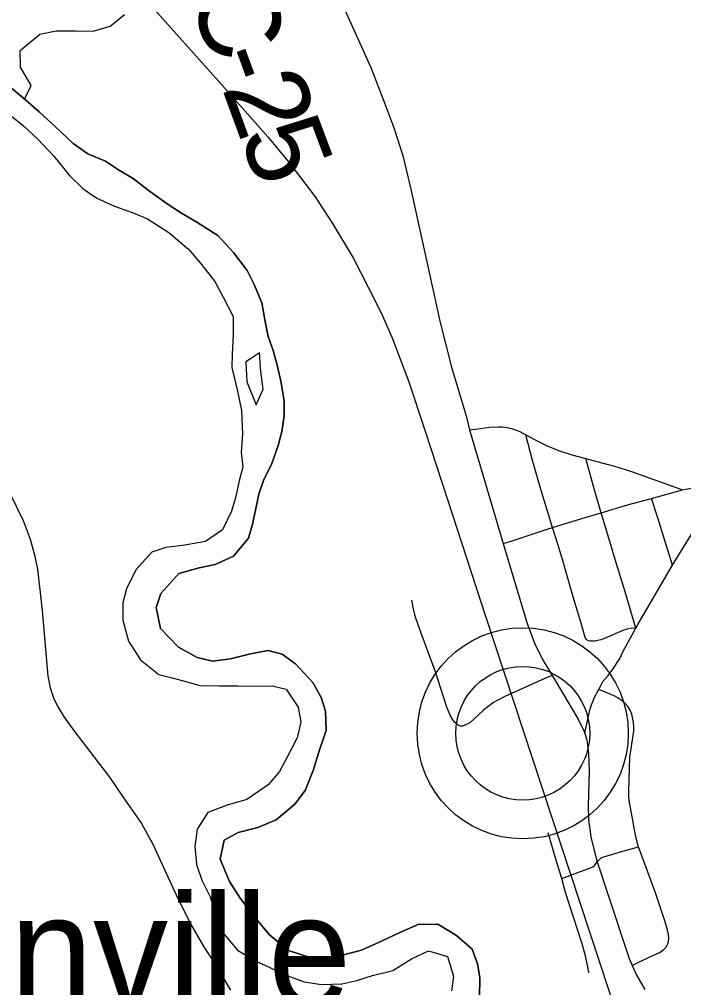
# Model space of a CAD drawing. Extents: x 0 to 34, y 0 to 22.
# Drawn here: x 6.658 to 7.127, y 19.04 to 19.722 of the extents above; entities that cross this region are included whole.
import ezdxf

# ---------------------------------------------------------------- set-up
doc = ezdxf.new("R2010")
doc.units = 0
for name, color, linetype in [('GM_X_County_Road', 7, 'Continuous'), ('GM_X_County_Road_Text', 7, 'Continuous'), ('GM_X_Major_River', 7, 'Continuous'), ('GM_X_Minor_River', 7, 'Continuous'), ('GM_X_Rail_Line', 7, 'Continuous'), ('GM_X_Township_Road', 7, 'Continuous'), ('GM_X_Unincorporated', 7, 'Continuous'), ('GM_X_Unincorporated_Location', 7, 'Continuous'), ('GM_X_Unincorporated_Text', 7, 'Continuous')]:
    doc.layers.add(name, color=color, linetype=linetype)

msp = doc.modelspace()

# ---------------------------------------------------------------- linework, layer by layer
at = {"layer": 'GM_X_County_Road'}
for points in [[(6.8659, 19.90723), (6.85719, 19.88713), (6.85353, 19.87534), (6.85094, 19.86327), (6.84944, 19.85102), (6.84896, 19.83868), (6.84959, 19.82636), (6.85148, 19.81418), (6.85452, 19.80221), (6.86073, 19.78792), (6.86585, 19.77648), (6.87184, 19.76461), (6.88429, 19.73703), (6.90598, 19.68854), (6.91561, 19.66344)], [(6.91561, 19.66344), (6.92203, 19.6467), (6.92852, 19.62638), (6.93433, 19.60265), (6.95482, 19.50873), (6.96301, 19.47731), (6.97326, 19.44282), (6.97549, 19.433), (6.99937, 19.35289), (7.01595, 19.29727), (7.02129, 19.28279), (7.02672, 19.27172), (7.03375, 19.26001), (7.0411, 19.24777), (7.05229, 19.22905), (7.0563, 19.22053), (7.05679, 19.21894), (7.05819, 19.21449), (7.05957, 19.20512), (7.05987, 19.19261), (7.05914, 19.16778), (7.05947, 19.15855), (7.06113, 19.14633), (7.06349, 19.13649), (7.06551, 19.12868), (7.07307, 19.10585), (7.08809, 19.06055), (7.0903, 19.05557), (7.09309, 19.04928), (7.09919, 19.03857)]]:
    msp.add_lwpolyline(points, dxfattribs=at)
at = {"layer": 'GM_X_Major_River'}
for p, q in [((6.66265, 19.66554), (6.64969, 19.67641)), ((6.67218, 19.65729), (6.66265, 19.66554)), ((6.64796, 19.65783), (6.6613, 19.64734)), ((6.68362, 19.64678), (6.67218, 19.65729)), ((6.6613, 19.64734), (6.67122, 19.63795)), ((6.69621, 19.63477), (6.68362, 19.64678)), ((6.67122, 19.63795), (6.68267, 19.62593)), ((6.70649, 19.62767), (6.69621, 19.63477)), ((6.71902, 19.62247), (6.70649, 19.62767)), ((6.68267, 19.62593), (6.69376, 19.61239)), ((6.72892, 19.61574), (6.71902, 19.62247)), ((6.73843, 19.61014), (6.72892, 19.61574)), ((6.69376, 19.61239), (6.7033, 19.603)), ((6.74909, 19.60191), (6.73843, 19.61014)), ((6.7033, 19.603), (6.71282, 19.59627)), ((6.76318, 19.5918), (6.74909, 19.60191)), ((6.71282, 19.59627), (6.72535, 19.5907)), ((6.72535, 19.5907), (6.73864, 19.58589)), ((6.73864, 19.58589), (6.74851, 19.58182)), ((6.77269, 19.58583), (6.76318, 19.5918)), ((6.78334, 19.57948), (6.77269, 19.58583)), ((6.74851, 19.58182), (6.76373, 19.5721)), ((6.79818, 19.57014), (6.78334, 19.57948)), ((6.76373, 19.5721), (6.77784, 19.5601)), ((6.80926, 19.55812), (6.79818, 19.57014)), ((6.77784, 19.5601), (6.78663, 19.54957)), ((6.81883, 19.54532), (6.80926, 19.55812)), ((6.78663, 19.54957), (6.79619, 19.53753)), ((6.82383, 19.53551), (6.81883, 19.54532)), ((6.79619, 19.53753), (6.80196, 19.5266)), ((6.82924, 19.52268), (6.82383, 19.53551)), ((6.80196, 19.5266), (6.80889, 19.51302)), ((6.83162, 19.50944), (6.82924, 19.52268)), ((6.80889, 19.51302), (6.809, 19.50014)), ((6.83361, 19.49884), (6.83162, 19.50944)), ((6.809, 19.50014), (6.80836, 19.48649)), ((6.8371, 19.48902), (6.83361, 19.49884)), ((6.80836, 19.48649), (6.80807, 19.47701)), ((6.82113, 19.48306), (6.81787, 19.48089)), ((6.82765, 19.48742), (6.82113, 19.48306)), ((6.82852, 19.47417), (6.82765, 19.48742)), ((6.84022, 19.47768), (6.8371, 19.48902)), ((6.80807, 19.47701), (6.812, 19.46037)), ((6.81787, 19.48089), (6.81875, 19.46688)), ((6.84258, 19.46747), (6.84022, 19.47768)), ((6.83015, 19.46167), (6.82852, 19.47417)), ((6.81875, 19.46688), (6.8252, 19.45072)), ((6.84498, 19.45347), (6.84258, 19.46747)), ((6.812, 19.46037), (6.81477, 19.44676)), ((6.8252, 19.45072), (6.83015, 19.46167)), ((6.84507, 19.44286), (6.84498, 19.45347)), ((6.81477, 19.44676), (6.81567, 19.43009)), ((6.84327, 19.43186), (6.84507, 19.44286)), ((6.81567, 19.43009), (6.81465, 19.4172)), ((6.84071, 19.42198), (6.84327, 19.43186)), ((6.83628, 19.40943), (6.84071, 19.42198)), ((6.81465, 19.4172), (6.81587, 19.40698)), ((6.83033, 19.39725), (6.83628, 19.40943)), ((6.81587, 19.40698), (6.81331, 19.3971)), ((6.81331, 19.3971), (6.81076, 19.38533)), ((6.82701, 19.38775), (6.83033, 19.39725)), ((6.82484, 19.37636), (6.82701, 19.38775)), ((6.81076, 19.38533), (6.80782, 19.37583)), ((6.80782, 19.37583), (6.8015, 19.36251)), ((6.82265, 19.36649), (6.82484, 19.37636)), ((6.8015, 19.36251), (6.78946, 19.35444)), ((6.81971, 19.35661), (6.82265, 19.36649)), ((6.78946, 19.35444), (6.7736, 19.35164)), ((6.80923, 19.34401), (6.81971, 19.35661)), ((6.75169, 19.3469), (6.74045, 19.33429)), ((6.7615, 19.35002), (6.75169, 19.3469)), ((6.7736, 19.35164), (6.7615, 19.35002)), ((6.79641, 19.33821), (6.80923, 19.34401)), ((6.74045, 19.33429), (6.73376, 19.32096)), ((6.77074, 19.33191), (6.78509, 19.33583)), ((6.78509, 19.33583), (6.79641, 19.33821)), ((6.758, 19.31778), (6.77074, 19.33191)), ((6.73376, 19.32096), (6.73119, 19.31109)), ((6.75468, 19.30789), (6.758, 19.31778)), ((6.73119, 19.31109), (6.7313, 19.29896)), ((6.75784, 19.29314), (6.75468, 19.30789)), ((6.7313, 19.29896), (6.73521, 19.28422)), ((6.77044, 19.27999), (6.75784, 19.29314)), ((6.73521, 19.28422), (6.74365, 19.27103)), ((6.78374, 19.27254), (6.77044, 19.27999)), ((6.79436, 19.26998), (6.78374, 19.27254)), ((6.80721, 19.27161), (6.79436, 19.26998)), ((6.82118, 19.27515), (6.80721, 19.27161)), ((6.83364, 19.27754), (6.82118, 19.27515)), ((6.8435, 19.27497), (6.83364, 19.27754)), ((6.85302, 19.26824), (6.8435, 19.27497)), ((6.74365, 19.27103), (6.75661, 19.26054)), ((6.86524, 19.25509), (6.85302, 19.26824)), ((6.75661, 19.26054), (6.76608, 19.25835)), ((6.76608, 19.25835), (6.77557, 19.25579)), ((6.77557, 19.25579), (6.78543, 19.25285)), ((6.78543, 19.25285), (6.79905, 19.25259)), ((6.79905, 19.25259), (6.81229, 19.25271)), ((6.81229, 19.25271), (6.8263, 19.25246)), ((6.8263, 19.25246), (6.83651, 19.25255)), ((6.83651, 19.25255), (6.84637, 19.25037)), ((6.87101, 19.24453), (6.86524, 19.25509)), ((6.84637, 19.25037), (6.8548, 19.23756)), ((6.87412, 19.23471), (6.87101, 19.24453)), ((6.8548, 19.23756), (6.85679, 19.22697)), ((6.87462, 19.22107), (6.87412, 19.23471)), ((6.85679, 19.22697), (6.85423, 19.21596)), ((6.87019, 19.20814), (6.87462, 19.22107)), ((6.85423, 19.21596), (6.84753, 19.20339)), ((6.84753, 19.20339), (6.84158, 19.19235)), ((6.86541, 19.19294), (6.87019, 19.20814)), ((6.84158, 19.19235), (6.83371, 19.1828)), ((6.85985, 19.17887), (6.86541, 19.19294)), ((6.83371, 19.1828), (6.81867, 19.17243)), ((6.85237, 19.16933), (6.85985, 19.17887)), ((6.81867, 19.17243), (6.8047, 19.16852)), ((6.83922, 19.15822), (6.85237, 19.16933)), ((6.79113, 19.16347), (6.78366, 19.15165)), ((6.8047, 19.16852), (6.79113, 19.16347)), ((6.82641, 19.1528), (6.83922, 19.15822)), ((6.78366, 19.15165), (6.78188, 19.13951)), ((6.80265, 19.14387), (6.81244, 19.14926)), ((6.81244, 19.14926), (6.82641, 19.1528)), ((6.79974, 19.13058), (6.80265, 19.14387)), ((6.78188, 19.13951), (6.78312, 19.12664)), ((6.80631, 19.11472), (6.79974, 19.13058)), ((6.78312, 19.12664), (6.787, 19.11568)), ((6.787, 19.11568), (6.79278, 19.10399)), ((6.81398, 19.10304), (6.80631, 19.11472)), ((6.79278, 19.10399), (6.79668, 19.09114)), ((6.82355, 19.09024), (6.81398, 19.10304)), ((6.79668, 19.09114), (6.80094, 19.07943)), ((6.83463, 19.07708), (6.82355, 19.09024)), ((6.93938, 19.08448), (6.92656, 19.07868)), ((6.95338, 19.08461), (6.93938, 19.08448)), ((6.96631, 19.07677), (6.95338, 19.08461)), ((6.80094, 19.07943), (6.81203, 19.06627)), ((6.84797, 19.06621), (6.83463, 19.07708)), ((6.92656, 19.07868), (6.91413, 19.07288)), ((6.97737, 19.06702), (6.96631, 19.07677)), ((6.91413, 19.07288), (6.89943, 19.0663)), ((6.98124, 19.05682), (6.97737, 19.06702)), ((6.81203, 19.06627), (6.82458, 19.0588)), ((6.86391, 19.06106), (6.84797, 19.06621)), ((6.87602, 19.06041), (6.86391, 19.06106)), ((6.88584, 19.06277), (6.87602, 19.06041)), ((6.89943, 19.0663), (6.88584, 19.06277)), ((6.9215, 19.0521), (6.93467, 19.06018)), ((6.93467, 19.06018), (6.94673, 19.06598)), ((6.94673, 19.06598), (6.96, 19.06193)), ((6.96, 19.06193), (6.96429, 19.04795)), ((6.82458, 19.0588), (6.83445, 19.05435)), ((6.83445, 19.05435), (6.84433, 19.04951)), ((6.98284, 19.04698), (6.98124, 19.05682)), ((6.84433, 19.04951), (6.85914, 19.04396)), ((6.89621, 19.04506), (6.90715, 19.04857)), ((6.90715, 19.04857), (6.9215, 19.0521)), ((6.96429, 19.04795), (6.96287, 19.03771)), ((6.98258, 19.03296), (6.98284, 19.04698)), ((6.85914, 19.04396), (6.87126, 19.04217)), ((6.87126, 19.04217), (6.88563, 19.04268)), ((6.88563, 19.04268), (6.89621, 19.04506))]:
    msp.add_line(p, q, dxfattribs=at)
for points in [[(6.64969, 19.67641), (6.66265, 19.66554), (6.67218, 19.65729), (6.68362, 19.64678), (6.69621, 19.63477), (6.70649, 19.62767), (6.71902, 19.62247), (6.72892, 19.61574), (6.73843, 19.61014), (6.74909, 19.60191), (6.76318, 19.5918), (6.77269, 19.58583), (6.78334, 19.57948), (6.79818, 19.57014), (6.80926, 19.55812), (6.81883, 19.54532), (6.82383, 19.53551), (6.82924, 19.52268), (6.83162, 19.50944), (6.83361, 19.49884), (6.8371, 19.48902), (6.84022, 19.47768), (6.84258, 19.46747), (6.84498, 19.45347), (6.84507, 19.44286), (6.84327, 19.43186), (6.84071, 19.42198), (6.83628, 19.40943), (6.83033, 19.39725), (6.82701, 19.38775), (6.82484, 19.37636), (6.82265, 19.36649), (6.81971, 19.35661), (6.80923, 19.34401), (6.79641, 19.33821), (6.78509, 19.33583), (6.77074, 19.33191), (6.758, 19.31778), (6.75468, 19.30789), (6.75784, 19.29314), (6.77044, 19.27999), (6.78374, 19.27254), (6.79436, 19.26998), (6.80721, 19.27161), (6.82118, 19.27515), (6.83364, 19.27754), (6.8435, 19.27497), (6.85302, 19.26824), (6.86524, 19.25509), (6.87101, 19.24453), (6.87412, 19.23471), (6.87462, 19.22107), (6.87019, 19.20814), (6.86541, 19.19294), (6.85985, 19.17887), (6.85237, 19.16933), (6.83922, 19.15822), (6.82641, 19.1528), (6.81244, 19.14926), (6.80265, 19.14387), (6.79974, 19.13058), (6.80631, 19.11472), (6.81398, 19.10304), (6.82355, 19.09024), (6.83463, 19.07708), (6.84797, 19.06621), (6.86391, 19.06106), (6.87602, 19.06041), (6.88584, 19.06277), (6.89943, 19.0663), (6.91413, 19.07288), (6.92656, 19.07868), (6.93938, 19.08448), (6.95338, 19.08461), (6.96631, 19.07677), (6.97737, 19.06702), (6.98124, 19.05682), (6.98284, 19.04698), (6.98258, 19.03296)], [(6.64796, 19.65783), (6.6613, 19.64734), (6.67122, 19.63795), (6.68267, 19.62593), (6.69376, 19.61239), (6.7033, 19.603), (6.71282, 19.59627), (6.72535, 19.5907), (6.73864, 19.58589), (6.74851, 19.58182), (6.76373, 19.5721), (6.77784, 19.5601), (6.78663, 19.54957), (6.79619, 19.53753), (6.80196, 19.5266), (6.80889, 19.51302), (6.809, 19.50014), (6.80836, 19.48649), (6.80807, 19.47701), (6.812, 19.46037), (6.81477, 19.44676), (6.81567, 19.43009), (6.81465, 19.4172), (6.81587, 19.40698), (6.81331, 19.3971), (6.81076, 19.38533), (6.80782, 19.37583), (6.8015, 19.36251), (6.78946, 19.35444), (6.7736, 19.35164), (6.7615, 19.35002), (6.75169, 19.3469), (6.74045, 19.33429), (6.73376, 19.32096), (6.73119, 19.31109), (6.7313, 19.29896), (6.73521, 19.28422), (6.74365, 19.27103), (6.75661, 19.26054), (6.76608, 19.25835), (6.77557, 19.25579), (6.78543, 19.25285), (6.79905, 19.25259), (6.81229, 19.25271), (6.8263, 19.25246), (6.83651, 19.25255), (6.84637, 19.25037), (6.8548, 19.23756), (6.85679, 19.22697), (6.85423, 19.21596), (6.84753, 19.20339), (6.84158, 19.19235), (6.83371, 19.1828), (6.81867, 19.17243), (6.8047, 19.16852), (6.79113, 19.16347), (6.78366, 19.15165), (6.78188, 19.13951), (6.78312, 19.12664), (6.787, 19.11568), (6.79278, 19.10399), (6.79668, 19.09114), (6.80094, 19.07943), (6.81203, 19.06627), (6.82458, 19.0588), (6.83445, 19.05435), (6.84433, 19.04951), (6.85914, 19.04396), (6.87126, 19.04217), (6.88563, 19.04268), (6.89621, 19.04506), (6.90715, 19.04857), (6.9215, 19.0521), (6.93467, 19.06018), (6.94673, 19.06598), (6.96, 19.06193), (6.96429, 19.04795), (6.96287, 19.03771)]]:
    msp.add_lwpolyline(points, dxfattribs=at)
at = {"layer": 'GM_X_Minor_River'}
for p, q in [((6.72236, 19.71762), (6.7325, 19.72567)), ((6.71028, 19.7141), (6.72236, 19.71762)), ((6.65894, 19.70037), (6.67284, 19.71186)), ((6.67284, 19.71186), (6.68417, 19.71424)), ((6.68417, 19.71424), (6.69779, 19.71437)), ((6.69779, 19.71437), (6.71028, 19.7141)), ((6.65905, 19.68862), (6.65894, 19.70037)), ((6.66672, 19.67581), (6.65905, 19.68862)), ((6.66196, 19.66612), (6.66672, 19.67581))]:
    msp.add_line(p, q, dxfattribs=at)
at = {"layer": 'GM_X_Rail_Line'}
msp.add_lwpolyline([(6.25626, 20.28694), (6.36015, 20.17053), (6.42862, 20.09337), (6.50745, 20.00502), (6.58044, 19.92352), (6.63572, 19.86139), (6.69184, 19.79859), (6.8029, 19.674), (6.83347, 19.63959), (6.849, 19.62072), (6.86687, 19.59717), (6.87906, 19.57847), (6.89359, 19.55425), (6.90411, 19.53371), (6.9133, 19.5155), (6.92098, 19.49797), (6.93284, 19.4669), (6.9442, 19.43283), (6.9604, 19.38323), (6.98662, 19.30256), (7.09368, 18.9774)], dxfattribs=at)
at = {"layer": 'GM_X_Township_Road'}
for points in [[(6.97549, 19.433), (6.98352, 19.43406), (6.98968, 19.43487), (6.99591, 19.43516), (6.99902, 19.43507), (7.00212, 19.43474), (7.00515, 19.43408), (7.00811, 19.43316), (7.01096, 19.43191), (7.01519, 19.4296), (7.02189, 19.42594), (7.03027, 19.42186), (7.03891, 19.4183), (7.04777, 19.41537), (7.0575, 19.41281), (7.06885, 19.40984), (7.07787, 19.40739), (7.08973, 19.40363), (7.10809, 19.39723), (7.11878, 19.39345), (7.1258, 19.39073)], [(7.03405, 19.36414), (7.02528, 19.39271), (7.01987, 19.41246), (7.01519, 19.4296)], [(7.09272, 19.29331), (7.08542, 19.31882), (7.07886, 19.33944), (7.07448, 19.35426), (7.06841, 19.37463), (7.06388, 19.38983), (7.0575, 19.41281)], [(6.99937, 19.35289), (7.00416, 19.35445), (7.03033, 19.36299), (7.03405, 19.36414), (7.05714, 19.37123), (7.06841, 19.37463), (7.08694, 19.38021), (7.10385, 19.38477), (7.1258, 19.39073), (7.13446, 19.39233), (7.1375, 19.39311), (7.14078, 19.39409), (7.14385, 19.39534), (7.14866, 19.39757)], [(6.65182, 19.38789), (6.66108, 19.36908), (6.666, 19.35599), (6.6693, 19.34402), (6.6711, 19.3347), (6.67302, 19.31837), (6.67449, 19.30577), (6.67848, 19.25939), (6.68003, 19.25114), (6.68227, 19.24412), (6.68522, 19.23834), (6.68994, 19.23055), (6.69713, 19.2205), (6.72181, 19.18832), (6.73135, 19.1743), (6.74436, 19.15556), (6.75244, 19.14099), (6.75907, 19.12676), (6.7688, 19.10545), (6.779, 19.08502), (6.78838, 19.0688), (6.79658, 19.05606), (6.80704, 19.03811)], [(7.11876, 19.33769), (7.11305, 19.35588), (7.10842, 19.37099), (7.10385, 19.38477)], [(7.05679, 19.21894), (7.05735, 19.22153), (7.05986, 19.23334), (7.06055, 19.23638), (7.0615, 19.23934), (7.06394, 19.24508), (7.06666, 19.24999), (7.06956, 19.2556), (7.07341, 19.26), (7.0767, 19.26439), (7.08164, 19.2718), (7.08384, 19.27702), (7.09272, 19.29331), (7.09414, 19.29592), (7.11876, 19.33769), (7.12424, 19.34688), (7.14385, 19.37857)], [(7.09272, 19.29331), (7.08886, 19.29316), (7.0868, 19.29264), (7.0837, 19.29159), (7.07064, 19.28607), (7.06808, 19.2851), (7.06603, 19.28448), (7.06413, 19.28422), (7.06237, 19.28409), (7.06087, 19.28416), (7.05968, 19.28435), (7.05853, 19.28483), (7.05778, 19.2855), (7.05715, 19.28664), (7.05658, 19.28833), (7.05427, 19.29673), (7.04912, 19.3138), (7.04115, 19.34158), (7.03958, 19.34701), (7.03816, 19.35167), (7.03405, 19.36414)], [(7.03375, 19.26001), (7.02867, 19.25775), (7.0005, 19.2452), (6.99502, 19.2424), (6.99239, 19.24081), (6.98747, 19.23716), (6.98514, 19.23516), (6.97839, 19.22884), (6.97603, 19.2269), (6.97343, 19.22534), (6.97059, 19.22418), (6.96923, 19.22424), (6.96842, 19.22444), (6.96766, 19.22485), (6.96534, 19.2268), (6.96353, 19.22924), (6.96205, 19.23187), (6.95971, 19.23754), (6.95311, 19.25795), (6.95125, 19.26376), (6.94049, 19.29233), (6.93755, 19.30104), (6.93607, 19.30698), (6.93483, 19.31299)], [(7.0903, 19.05557), (7.09551, 19.05821), (7.10224, 19.06131), (7.10954, 19.06466), (7.11216, 19.06627), (7.11429, 19.06845), (7.11558, 19.07121), (7.11603, 19.07426), (7.11583, 19.07733), (7.11525, 19.08036), (7.11358, 19.08633), (7.10663, 19.10677), (7.09707, 19.13285), (7.09481, 19.13907), (7.09402, 19.14157), (7.09247, 19.14752), (7.08807, 19.17181), (7.08779, 19.17486), (7.08779, 19.17794), (7.08858, 19.20251), (7.08895, 19.20551), (7.09058, 19.21454), (7.09132, 19.22065), (7.09137, 19.22373), (7.09107, 19.22673), (7.08998, 19.23275), (7.08877, 19.2355), (7.08707, 19.23804), (7.08503, 19.24035), (7.08273, 19.24238), (7.08019, 19.24413), (7.07749, 19.24559), (7.07463, 19.24674), (7.06666, 19.24999)], [(7.05981, 19.05027), (7.0593, 19.05334), (7.05727, 19.06244), (7.05473, 19.07144), (7.04336, 19.10706), (7.04056, 19.11691), (7.03652, 19.13038), (7.03108, 19.14893)], [(7.04056, 19.11691), (7.05581, 19.12246), (7.06154, 19.12456), (7.0626, 19.12515), (7.06359, 19.12597), (7.06551, 19.12868), (7.0685, 19.13135), (7.0702, 19.13212), (7.0837, 19.13608), (7.09481, 19.13907)]]:
    msp.add_lwpolyline(points, dxfattribs=at)
at = {"layer": 'GM_X_Unincorporated'}
for radius in [0.0744, 0.04716]:
    msp.add_circle((7.01313, 19.21922), radius, dxfattribs=at)
at = {"layer": 'GM_X_Unincorporated_Location'}
msp.add_line((7.01313, 19.21922), (7.01313, 19.21922), dxfattribs=at)

# ---------------------------------------------------------------- texts
at = {"layer": 'GM_X_County_Road_Text'}
for s, rotation, p in [('C', 289.99645, (6.77687, 19.74)), ('-', 290.02086, (6.79283, 19.69612)), ('2', 290.16712, (6.80087, 19.67405)), ('5', 290.58246, (6.8131, 19.64078))]:
    msp.add_text(s, height=0.05682, rotation=rotation, dxfattribs=at).set_placement(p)
at = {"layer": 'GM_X_Unincorporated_Text'}
msp.add_text('Haydenville', height=0.0789773, rotation=0.00001, dxfattribs=at).set_placement((6.3463, 19.0262))

doc.saveas('drawing.dxf')
